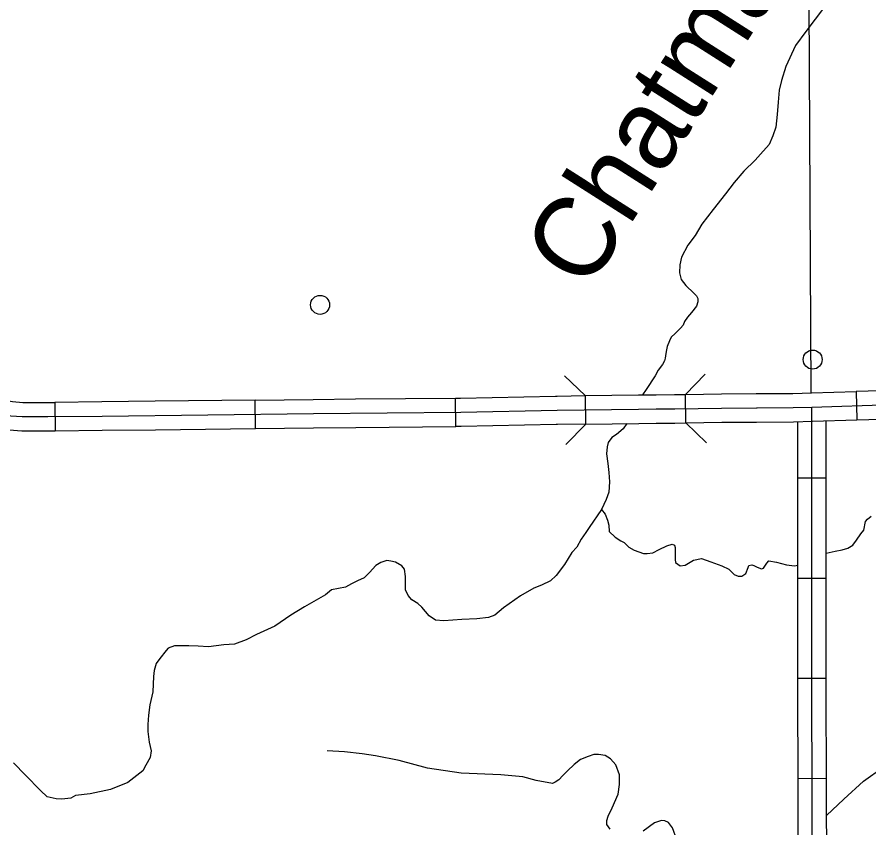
# Model space of a CAD drawing. Extents: x 22866 to 28196, y 1324810 to 1328105.
# Drawn here: x 25357.6 to 25465.4, y 1325979.6 to 1326082.2 of the extents above; entities that cross this region are included whole.
import ezdxf

# ---------------------------------------------------------------- set-up
doc = ezdxf.new("R2010")
doc.units = 0
for name, color, linetype in [('Level 31', 7, 'Continuous'), ('Level 32', 7, 'Continuous'), ('Level 35', 7, 'Continuous'), ('Level 38', 7, 'Continuous'), ('Level 46', 7, 'Continuous'), ('Level 5', 7, 'Continuous'), ('Level 56', 7, 'Continuous')]:
    doc.layers.add(name, color=color, linetype=linetype)

msp = doc.modelspace()

# ---------------------------------------------------------------- linework, layer by layer
at = {"layer": 'Level 31'}
for p, q in [((25463.75, 1326034.84), (25463.86, 1326031.24)), ((25362.41, 1326033.47), (25362.44, 1326029.87)), ((25387.79, 1326030.16), (25387.75, 1326033.76)), ((25413.14, 1326030.42), (25413.1, 1326034.02)), ((25413.1, 1326034.02), (25413.1, 1326034.02))]:
    msp.add_line(p, q, dxfattribs=at)
for points in [[(25351.14, 1326036.1), (25355.87, 1326033.78), (25357.07, 1326033.56), (25358.35, 1326033.46), (25361.51, 1326033.46), (25362.41, 1326033.47)], [(25429.49, 1326034.32), (25436.22, 1326034.41), (25438.45, 1326034.43)], [(25438.45, 1326034.43), (25440.78, 1326034.45), (25442.16, 1326034.47)], [(25442.22, 1326030.87), (25442.16, 1326034.47), (25446.72, 1326034.55), (25451.13, 1326034.57)], [(25451.13, 1326034.57), (25455.76, 1326034.6), (25458.12, 1326034.67), (25463.75, 1326034.84)], [(25476.41, 1326035.19), (25472.74, 1326035.05), (25468.28, 1326034.98), (25463.75, 1326034.84)], [(25375.08, 1326033.61), (25368.37, 1326033.53), (25362.41, 1326033.47)], [(25387.75, 1326033.76), (25375.08, 1326033.61)], [(25387.75, 1326033.76), (25395.1, 1326033.85), (25400.43, 1326033.9)], [(25400.43, 1326033.9), (25413.1, 1326034.02)], [(25413.1, 1326034.02), (25413.73, 1326034.02), (25425.75, 1326034.27)], [(25425.75, 1326034.27), (25425.93, 1326034.27), (25429.49, 1326034.32), (25429.54, 1326030.72)], [(25349.55, 1326032.86), (25354.73, 1326030.32), (25356.62, 1326029.98), (25358.22, 1326029.86), (25361.52, 1326029.86), (25362.44, 1326029.87)], [(25438.46, 1326032.63), (25440.81, 1326032.65), (25446.74, 1326032.75), (25451.14, 1326032.77)], [(25439.29, 1325954.64), (25440.69, 1325957.94), (25441.46, 1325959.35), (25442.23, 1325960.83), (25442.87, 1325964.27), (25443.29, 1325966.17), (25443.64, 1325967.22), (25444.97, 1325968.35), (25446.73, 1325968.98), (25451.99, 1325969.26), (25456, 1325969.61), (25457.54, 1325970.24), (25458.17, 1325971.09), (25458.24, 1325972.7), (25458.17, 1325996.39), (25458.17, 1326011.29), (25458.17, 1326032.87)], [(25451.14, 1326032.77), (25455.79, 1326032.8)], [(25455.79, 1326032.8), (25458.17, 1326032.87), (25468.33, 1326033.18)], [(25451.15, 1326030.97), (25455.82, 1326031), (25458.23, 1326031.07), (25463.86, 1326031.24)], [(25463.86, 1326031.24), (25468.37, 1326031.38), (25472.83, 1326031.45), (25476.54, 1326031.59)], [(25375.12, 1326030.01), (25387.79, 1326030.16)], [(25387.79, 1326030.16), (25395.14, 1326030.25), (25400.46, 1326030.3)], [(25400.46, 1326030.3), (25413.14, 1326030.42)], [(25425.83, 1326030.67), (25413.79, 1326030.42), (25413.14, 1326030.42)], [(25429.54, 1326030.72), (25425.99, 1326030.67), (25425.83, 1326030.67)], [(25429.54, 1326030.72), (25436.26, 1326030.81), (25438.48, 1326030.83)], [(25438.48, 1326030.83), (25440.83, 1326030.85), (25442.22, 1326030.87)], [(25442.22, 1326030.87), (25446.76, 1326030.95), (25451.15, 1326030.97)], [(25362.44, 1326029.87), (25368.41, 1326029.93), (25375.12, 1326030.01)]]:
    msp.add_lwpolyline(points, dxfattribs=at)
at = {"layer": 'Level 32'}
for p, q in [((25459.97, 1326023.86), (25456.37, 1326023.86)), ((25459.97, 1326011.19), (25456.37, 1326011.19)), ((25459.97, 1325998.51), (25456.37, 1325998.51)), ((25460.01, 1325985.85), (25456.41, 1325985.83))]:
    msp.add_line(p, q, dxfattribs=at)
for points in [[(25459.97, 1326023.86), (25459.97, 1326031.12)], [(25456.37, 1326023.86), (25456.37, 1326031)], [(25456.37, 1326011.19), (25456.37, 1326011.29), (25456.37, 1326023.86)], [(25459.97, 1326011.19), (25459.97, 1326011.29), (25459.97, 1326023.86)], [(25456.37, 1325998.51), (25456.37, 1326011.19)], [(25459.97, 1325998.51), (25459.97, 1326011.19)], [(25456.41, 1325985.83), (25456.37, 1325996.39), (25456.37, 1325998.51)], [(25460.01, 1325985.85), (25459.97, 1325996.4), (25459.97, 1325998.51)], [(25456.44, 1325973.16), (25456.41, 1325985.83)], [(25460.04, 1325973.17), (25460.01, 1325985.85)]]:
    msp.add_lwpolyline(points, dxfattribs=at)
at = {"layer": 'Level 35'}
for points in [[(25459.74, 1326083.53), (25457.39, 1326080.39), (25456.08, 1326078.63), (25454.88, 1326075.96), (25454.33, 1326074.19), (25454.02, 1326072.98), (25453.89, 1326071.47), (25453.76, 1326069.92), (25453.58, 1326068.3), (25453.24, 1326067.2), (25452.74, 1326066.1), (25451.67, 1326064.87), (25451, 1326064.11), (25449.56, 1326062.72), (25448.31, 1326061.28), (25447.23, 1326059.87), (25445.69, 1326057.86), (25444.23, 1326056.02), (25443.39, 1326054.59), (25442.45, 1326053.37), (25441.67, 1326051.83), (25441.46, 1326050.89), (25441.41, 1326049.87)], [(25441.41, 1326049.87), (25441.61, 1326049), (25442.22, 1326048.24), (25443.21, 1326047.3), (25443.55, 1326046.96), (25443.73, 1326046.62), (25443.73, 1326046.2), (25443.58, 1326045.65), (25442.95, 1326044.84), (25442.43, 1326044.24), (25442.03, 1326043.69), (25441.88, 1326043.22), (25441.54, 1326042.88), (25440.88, 1326042.2), (25440.36, 1326041.73), (25440.15, 1326041.26), (25439.86, 1326040.55), (25439.71, 1326039.92), (25439.65, 1326039.37), (25439.6, 1326039.06), (25439.5, 1326038.72), (25439.26, 1326038.25), (25438.71, 1326037.54), (25438.32, 1326036.84)], [(25438.32, 1326036.84), (25437.22, 1326035.1), (25436.74, 1326034.42)], [(25434.76, 1326030.79), (25434.3, 1326030.13), (25433.43, 1326029.4), (25432.86, 1326029.01), (25432.41, 1326028.38), (25432.26, 1326027.86), (25432.18, 1326026.94), (25432.34, 1326025.74), (25432.49, 1326024.61)], [(25432.49, 1326024.61), (25432.57, 1326023.4), (25432.47, 1326022.09), (25432.13, 1326021.18), (25431.55, 1326019.92), (25429.98, 1326017.64), (25429.56, 1326016.99), (25428.96, 1326016.15), (25428.41, 1326015.16), (25427.81, 1326014.48), (25426.85, 1326012.96), (25425.83, 1326011.55), (25425.1, 1326010.89), (25423.95, 1326010.34), (25423, 1326009.95)], [(25431.55, 1326019.92), (25432.01, 1326019.33), (25432.3, 1326018.57), (25432.46, 1326017.94), (25432.51, 1326017.13), (25433.27, 1326016.4), (25434, 1326015.95), (25434.42, 1326015.75), (25434.99, 1326015.12), (25435.67, 1326014.75), (25436.88, 1326014.33), (25437.32, 1326014.33), (25438.03, 1326014.44), (25438.86, 1326014.86), (25439.8, 1326015.33), (25440.48, 1326015.54), (25440.8, 1326015.38), (25440.87, 1326015.09), (25440.87, 1326014.46), (25440.87, 1326013.6), (25440.93, 1326013.21), (25441.48, 1326012.76), (25442.13, 1326012.87), (25443.2, 1326013.5), (25444.19, 1326013.7), (25445.4, 1326013.29), (25446.76, 1326012.76), (25447.64, 1326012.34)], [(25459.97, 1326014.4), (25461.12, 1326014.64), (25462.01, 1326014.8), (25462.72, 1326015.03), (25463.32, 1326015.4), (25463.81, 1326016.03), (25464.36, 1326016.84), (25464.75, 1326017.31), (25464.94, 1326018.38), (25465.2, 1326018.69), (25465.67, 1326019.06)], [(25423, 1326009.95), (25421.31, 1326008.97), (25419.17, 1326007.48), (25418.07, 1326006.54), (25417.26, 1326006.25), (25415.8, 1326006.06), (25413.89, 1326005.99), (25411.62, 1326005.8), (25410.57, 1326005.91), (25409.76, 1326006.46), (25408.82, 1326007.53), (25408.3, 1326008), (25407.56, 1326008.47), (25407.09, 1326009.02), (25406.78, 1326009.73), (25406.78, 1326010.3), (25406.75, 1326010.9), (25406.75, 1326011.43), (25406.65, 1326012.37), (25406.28, 1326012.79), (25405.5, 1326013.23), (25404.92, 1326013.39), (25404.4, 1326013.44), (25403.64, 1326013.21), (25402.99, 1326012.81), (25402.21, 1326011.95), (25401.53, 1326011.24), (25400.7, 1326010.88), (25399.91, 1326010.51), (25399.15, 1326010.09), (25397.4, 1326009.75), (25396.62, 1326009.1), (25394, 1326007.61), (25392.25, 1326006.54)], [(25447.64, 1326012.34), (25448.32, 1326011.69), (25448.84, 1326011.45), (25449.31, 1326011.45), (25449.81, 1326011.82), (25450.12, 1326012.58), (25450.2, 1326012.81), (25450.57, 1326012.92), (25450.8, 1326012.84), (25451.25, 1326012.61), (25451.8, 1326012.4), (25452.06, 1326012.5), (25452.47, 1326013.13), (25452.71, 1326013.42), (25453.7, 1326013.23), (25454.96, 1326012.89), (25455.95, 1326012.76), (25456.37, 1326012.86)], [(25392.25, 1326006.54), (25390.22, 1326005.16), (25387.92, 1326004.08), (25386.59, 1326003.4), (25385.15, 1326002.85), (25383.79, 1326002.78), (25381.83, 1326002.54), (25380.55, 1326002.59), (25379.35, 1326002.67), (25378.3, 1326002.67), (25377.54, 1326002.65), (25376.73, 1326002.36), (25376.48, 1326002.05), (25375.69, 1326001.06), (25375.22, 1326000.43), (25375.12, 1326000.14), (25374.99, 1325999.54), (25374.88, 1325998.78), (25374.78, 1325996.85), (25374.44, 1325995.2), (25374.26, 1325993.89), (25374.15, 1325992.69), (25374.15, 1325991.8), (25374.33, 1325990.44), (25374.57, 1325989.37), (25374.47, 1325988.53), (25373.92, 1325987.56), (25373.52, 1325986.85)], [(25460.02, 1325981.17), (25462.22, 1325983.23), (25464.68, 1325985.53), (25467.19, 1325987.31), (25469.07, 1325988.78), (25470.12, 1325989.56), (25471.32, 1325989.98), (25472.78, 1325990.24), (25474.3, 1325989.93), (25476.02, 1325989.62), (25477.28, 1325989.82), (25478.9, 1325990.87), (25481.62, 1325993.28), (25482.25, 1325994.27)], [(25432.64, 1325979.46), (25432.22, 1325980.04), (25432.22, 1325980.54), (25432.41, 1325981.11), (25432.88, 1325982.13), (25433.66, 1325983.87), (25433.84, 1325985.12), (25433.82, 1325986.33), (25433.35, 1325987.58), (25432.67, 1325988.37), (25432.01, 1325988.76), (25431.18, 1325988.92), (25430.6, 1325988.92), (25429.87, 1325988.65), (25428.88, 1325988.26), (25428.09, 1325987.63), (25427.26, 1325986.82), (25426.68, 1325986.22), (25426.16, 1325985.7), (25425.69, 1325985.41), (25425.35, 1325985.23), (25423.29, 1325985.59), (25421.62, 1325986.06), (25418.8, 1325986.33), (25413.81, 1325986.53), (25409.55, 1325987.19), (25405.96, 1325988.16), (25402.96, 1325988.73), (25401.26, 1325988.99), (25399.04, 1325989.23), (25396.85, 1325989.36)], [(25365.01, 1325983.73), (25364.41, 1325983.36), (25363.28, 1325983.23), (25362.58, 1325983.28), (25361.45, 1325983.52), (25360.59, 1325984.36), (25358.71, 1325986.27), (25357.17, 1325987.84)], [(25373.52, 1325986.85), (25371.64, 1325985.35), (25369.43, 1325984.49), (25366.89, 1325983.91), (25365.01, 1325983.73)], [(25441.08, 1325978.08), (25440.54, 1325979.62), (25440.01, 1325980.3), (25439.57, 1325980.51), (25439.12, 1325980.54), (25438.26, 1325980.25), (25436.8, 1325979.2)]]:
    msp.add_lwpolyline(points, dxfattribs=at)
at = {"layer": 'Level 38'}
for points in [[(25426.88, 1326036.83), (25429.48, 1326034.33)], [(25442.16, 1326034.46), (25444.65, 1326037.05)], [(25429.56, 1326030.73), (25427.06, 1326028.14)], [(25444.83, 1326028.36), (25442.23, 1326030.86)]]:
    msp.add_lwpolyline(points, dxfattribs=at)
at = {"layer": 'Level 46'}
msp.add_lwpolyline([(25336.04, 1326041.45), (25341.64, 1326038.8), (25350.14, 1326034.58), (25355.3, 1326032.05), (25356.85, 1326031.77), (25358.28, 1326031.66), (25361.51, 1326031.66), (25368.39, 1326031.73), (25395.12, 1326032.05), (25413.76, 1326032.22), (25425.96, 1326032.47), (25436.24, 1326032.61), (25440.81, 1326032.65), (25446.74, 1326032.75), (25455.79, 1326032.8)], dxfattribs=at)
at = {"layer": 'Level 5'}
msp.add_lwpolyline([(25457.45, 1326150.02), (25458.02, 1326034.66)], dxfattribs=at)
at = {"layer": 'Level 56'}
for centre in [(25395.95, 1326045.81), (25458.26, 1326038.88)]:
    msp.add_circle(centre, 1.2, dxfattribs=at)

# ---------------------------------------------------------------- texts
at = {"layer": 'Level 35'}
msp.add_text('Chatman', height=10.139, rotation=57.5271, dxfattribs=at).set_placement((25429.75, 1326047.35))

doc.saveas('drawing.dxf')
